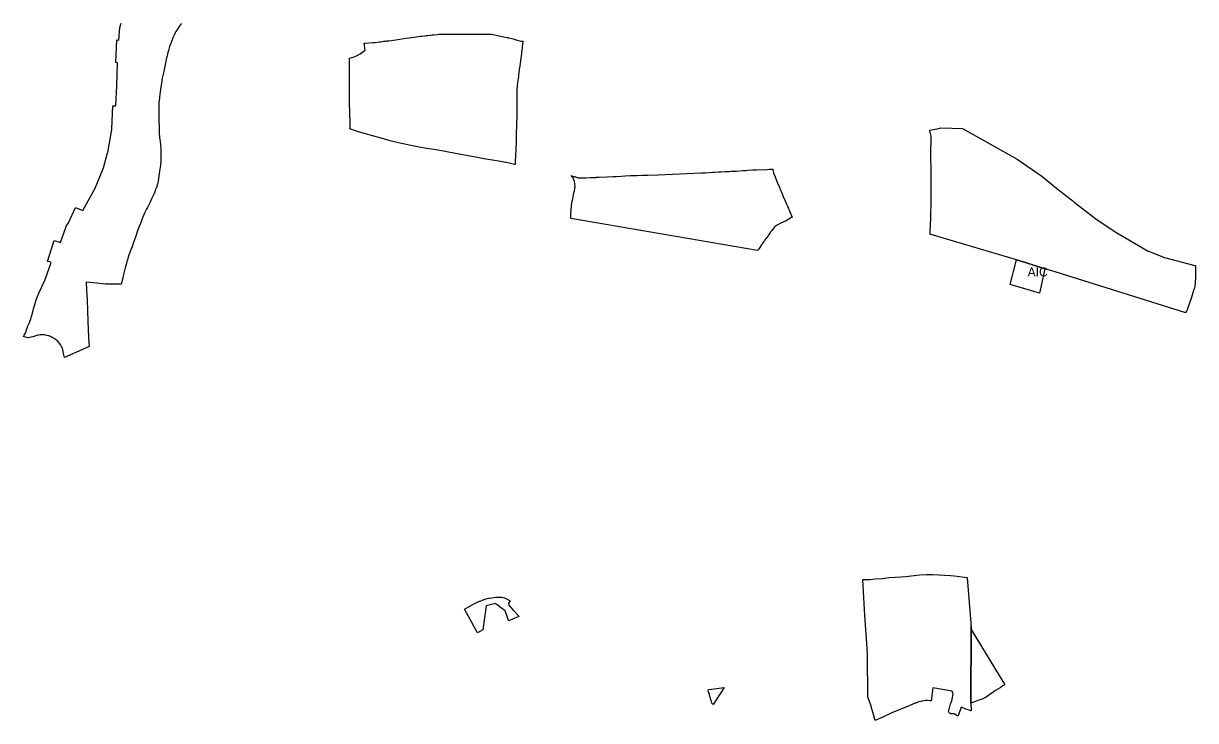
# Model space of a CAD drawing. Extents: x 603332 to 610661, y 4407453 to 4413433.
# Drawn here: x 606609 to 608167, y 4407735 to 4408661 of the extents above; entities that cross this region are included whole.
import ezdxf

# ---------------------------------------------------------------- set-up
doc = ezdxf.new("R2010")
doc.units = 0
for name, color, linetype in [('Sistema General-Activitats i instal·lacions complementàries', 7, 'Continuous'), ('Sistema General-Equipament Privat de Costes', 7, 'Continuous'), ('Sistema General-Espai Lliure Públic', 7, 'Continuous'), ('Sistema General-Espai Lliure Públic-Sòl Rústic', 7, 'Continuous')]:
    doc.layers.add(name, color=color, linetype=linetype)

msp = doc.modelspace()

# ---------------------------------------------------------------- linework, layer by layer
at = {"layer": 'Sistema General-Activitats i instal·lacions complementàries'}
msp.add_lwpolyline([(607967, 4408335.3), (607960, 4408303), (607921, 4408314.2), (607929.2, 4408347), (607941.1, 4408343.4)], close=True, dxfattribs=at)
at = {"layer": 'Sistema General-Equipament Privat de Costes'}
for points in [[(607248.3, 4407897.9), (607248.6, 4407897.8), (607252.2, 4407896.1), (607256.1, 4407893.7), (607254, 4407890.9), (607254.4, 4407888.2), (607257.4, 4407884.8), (607260.4, 4407881.5), (607261.3, 4407880.5), (607267.8, 4407873.4), (607268, 4407873.1), (607263.8, 4407871.4), (607262.3, 4407870.7), (607261.8, 4407870.5), (607261.7, 4407870.4), (607260.1, 4407869.7), (607254.4, 4407867.3), (607254.1, 4407867.9), (607252.4, 4407872.9), (607249.6, 4407880.7), (607241.6, 4407886.5), (607241.6, 4407886.6), (607238.4, 4407888.9), (607238.3, 4407889), (607236.7, 4407890.2), (607224.4, 4407887.3), (607220, 4407855.2), (607213, 4407851.4), (607195.6, 4407882.8), (607198.8, 4407884.5), (607206.5, 4407888.8), (607210.7, 4407891), (607211.3, 4407891.3), (607212.8, 4407892), (607213.1, 4407892.2), (607213.8, 4407892.5), (607214, 4407892.6), (607215.5, 4407893.2), (607216.3, 4407893.5), (607218.8, 4407894.4), (607221.3, 4407895.4), (607221.7, 4407895.5), (607222.2, 4407895.7), (607222.3, 4407895.7), (607222.8, 4407895.9), (607224.8, 4407896.5), (607225.8, 4407896.8), (607227.6, 4407897.2), (607228.6, 4407897.4), (607232.1, 4407897.9), (607236.8, 4407898.6), (607241.7, 4407898.9), (607242.9, 4407898.9), (607244.3, 4407898.7), (607245.3, 4407898.5)], [(607913.8, 4407782.5), (607912.7, 4407781.7), (607912, 4407781.3), (607909.9, 4407779.9), (607907.3, 4407778.2), (607904.3, 4407776.4), (607901.3, 4407774.5), (607890.8, 4407766.9), (607888.8, 4407765.6), (607886.2, 4407764.3), (607883.7, 4407763.1), (607880.6, 4407762.1), (607880.4, 4407762), (607877.8, 4407761.2), (607871.1, 4407758.8), (607868.7, 4407757.9), (607868.7, 4407757.9), (607868.7, 4407763.2), (607868.9, 4407851.8), (607868.9, 4407858.1), (607868.9, 4407859), (607868.9, 4407859), (607868.9, 4407859), (607868.9, 4407860.6), (607868.9, 4407858.9), (607869.1, 4407857.3), (607869.4, 4407855.7), (607869.9, 4407854.1), (607870.2, 4407853.4), (607912.6, 4407784.5)], [(607526.1, 4407756.2), (607524.5, 4407757.7), (607524, 4407759.6), (607523.5, 4407761.3), (607522.7, 4407763.6), (607522.6, 4407764.1), (607522.2, 4407765.5), (607521.4, 4407769.3), (607520.5, 4407771.5), (607519.6, 4407774.2), (607519.8, 4407776.1), (607524.1, 4407776.6), (607540.9, 4407778.4)]]:
    msp.add_lwpolyline(points, close=True, dxfattribs=at)
at = {"layer": 'Sistema General-Espai Lliure Públic'}
msp.add_lwpolyline([(606819.4, 4408661.4), (606818.5, 4408660.2), (606817.2, 4408658.6), (606816.7, 4408657.8), (606813.8, 4408653.3), (606812.2, 4408650.7), (606811.7, 4408649.8), (606811.1, 4408648.7), (606809.8, 4408646), (606808.1, 4408642.4), (606807, 4408639.6), (606804.2, 4408631.7), (606803.8, 4408630.7), (606802.7, 4408627.3), (606802.1, 4408625.3), (606801.5, 4408622.9), (606800.3, 4408618.4), (606799.7, 4408615.8), (606795.9, 4408597.4), (606794, 4408588.5), (606793.6, 4408586.4), (606793.2, 4408584.5), (606792.9, 4408582.4), (606792.4, 4408579.5), (606791.6, 4408573.6), (606790.3, 4408563.7), (606790.1, 4408561.7), (606789.8, 4408558.8), (606789.6, 4408556.7), (606789.4, 4408552.8), (606789.2, 4408548.8), (606789.2, 4408545.5), (606789.2, 4408541.7), (606789.5, 4408531.3), (606789.7, 4408525), (606789.8, 4408520.3), (606790, 4408516), (606790.5, 4408509.2), (606790.7, 4408507.2), (606791.5, 4408500.9), (606791.7, 4408498.5), (606791.9, 4408495), (606792, 4408493.4), (606792.1, 4408489.6), (606792.1, 4408483.4), (606792, 4408479.5), (606791.9, 4408477.3), (606791.7, 4408474.5), (606791.6, 4408473), (606790.9, 4408467.6), (606788.7, 4408452.1), (606788.5, 4408451.1), (606788.2, 4408449.6), (606787.3, 4408446.5), (606786.3, 4408443.2), (606785.2, 4408440.5), (606783.5, 4408436.3), (606780.2, 4408429), (606777.8, 4408423.9), (606776.8, 4408421.8), (606774.2, 4408416.6), (606773.1, 4408414.5), (606771.1, 4408410.9), (606770.2, 4408409), (606768.9, 4408405.9), (606767.7, 4408402.8), (606766.6, 4408400.1), (606764.9, 4408395.5), (606763.3, 4408391.3), (606762.5, 4408389.3), (606761.7, 4408387.2), (606758.8, 4408378.4), (606756.4, 4408371.7), (606754.6, 4408366.3), (606754.3, 4408365.3), (606753.7, 4408364), (606753.1, 4408362.7), (606751.5, 4408358.4), (606750.1, 4408354.7), (606749.6, 4408353.3), (606749.2, 4408352), (606747.6, 4408347.1), (606747.4, 4408346.3), (606747.1, 4408345.3), (606746.8, 4408343.7), (606746.5, 4408342.7), (606744.8, 4408336.3), (606742.1, 4408326), (606741.4, 4408323.1), (606741.1, 4408321.7), (606740.7, 4408319.6), (606740.3, 4408317.5), (606740.2, 4408316.8), (606740, 4408316.5), (606739.5, 4408314.9), (606739.2, 4408314.9), (606724.3, 4408314.7), (606718.6, 4408315), (606707.1, 4408315.9), (606693, 4408317.4), (606693.4, 4408306.7), (606694, 4408293.7), (606694.5, 4408280.1), (606695.1, 4408265.5), (606696.1, 4408244), (606696.9, 4408231.7), (606671, 4408220.5), (606663.9, 4408217.4), (606662.9, 4408222.7), (606662.4, 4408224.7), (606661.7, 4408227.8), (606661.3, 4408229), (606660.8, 4408230.6), (606660.1, 4408232), (606659, 4408233.9), (606658, 4408235.3), (606656.4, 4408237.3), (606655.9, 4408237.8), (606654.2, 4408239.7), (606653.5, 4408240.4), (606652.1, 4408241.4), (606651.1, 4408242.1), (606649.6, 4408243), (606649.1, 4408243.3), (606648.4, 4408243.7), (606646.7, 4408244.5), (606645.3, 4408245.1), (606643.2, 4408245.9), (606642.2, 4408246.2), (606640.6, 4408246.6), (606639.1, 4408247), (606637.2, 4408247.3), (606636.4, 4408247.4), (606635.6, 4408247.4), (606632.7, 4408247.3), (606631.7, 4408247.3), (606629.6, 4408247), (606628.4, 4408246.8), (606627.2, 4408246.4), (606625.4, 4408245.9), (606623.9, 4408245.4), (606621.9, 4408244.6), (606615.4, 4408243.4), (606609.5, 4408245), (606610.5, 4408247), (606612.7, 4408250.5), (606613.2, 4408252.9), (606614.1, 4408255.4), (606615, 4408257.7), (606615.5, 4408259.5), (606615.8, 4408260.2), (606617.3, 4408263.1), (606617.5, 4408263.8), (606618, 4408265.4), (606619.1, 4408268), (606619.8, 4408271.2), (606620.1, 4408272), (606620.5, 4408272.8), (606620.9, 4408275), (606621.9, 4408278.1), (606623, 4408281.8), (606624.7, 4408287.9), (606626.4, 4408293.9), (606629.2, 4408300.8), (606630, 4408302.8), (606633.4, 4408310.2), (606638.4, 4408321.2), (606646.4, 4408343.6), (606643.9, 4408344.4), (606641.3, 4408345.1), (606650.2, 4408372.8), (606658.8, 4408370.1), (606666.3, 4408391.5), (606666.3, 4408391.7), (606667.4, 4408393.7), (606669.2, 4408396.3), (606669.2, 4408396.3), (606678.7, 4408416.9), (606688.5, 4408412.5), (606704.9, 4408442.4), (606704.9, 4408442.4), (606715.7, 4408469.6), (606721.4, 4408489.4), (606721.5, 4408490), (606727, 4408520.6), (606727, 4408521.1), (606728.5, 4408551.8), (606732.3, 4408551.7), (606733.4, 4408578.3), (606734.6, 4408609), (606732.4, 4408609.4), (606733.6, 4408639.4), (606736.4, 4408639.2), (606737.8, 4408656.1), (606739.5, 4408661.8)], dxfattribs=at)
for points in [[(607263, 4408473.7), (607262.3, 4408473.8), (607251.5, 4408476.3), (607249.9, 4408476.7), (607241.4, 4408478.1), (607235.5, 4408479.1), (607221.4, 4408481.6), (607216.9, 4408482.4), (607210.2, 4408483.6), (607183.6, 4408488.4), (607170.1, 4408491), (607157.8, 4408493.2), (607151.9, 4408494.2), (607145.1, 4408495.3), (607133.2, 4408497.4), (607126.4, 4408498.7), (607113.9, 4408501.2), (607108, 4408502.5), (607096.7, 4408505.3), (607092.3, 4408506.6), (607081.7, 4408509.6), (607075.1, 4408511.5), (607062.2, 4408515.1), (607053.5, 4408517.6), (607043.2, 4408521.4), (607043.5, 4408522.3), (607043.6, 4408528.7), (607043.1, 4408542.5), (607043.1, 4408542.6), (607042.8, 4408556.5), (607042.8, 4408558), (607042.9, 4408575.4), (607043, 4408585.4), (607042.6, 4408615.2), (607045.8, 4408616), (607049, 4408616.8), (607051.1, 4408617.9), (607052.8, 4408618.8), (607053.9, 4408619.4), (607056.9, 4408621), (607059.9, 4408623.2), (607063.5, 4408625.9), (607062.5, 4408635), (607063.8, 4408635.1), (607073.7, 4408635.9), (607076.7, 4408636.2), (607082.5, 4408636.8), (607083.3, 4408636.9), (607083.7, 4408637), (607083.7, 4408637), (607084.2, 4408637.1), (607084.5, 4408637.1), (607086.2, 4408637.3), (607088.4, 4408637.6), (607089.4, 4408637.7), (607089.7, 4408637.7), (607089.7, 4408637.7), (607089.7, 4408637.7), (607089.8, 4408637.7), (607089.9, 4408637.7), (607089.9, 4408637.7), (607089.9, 4408637.7), (607090, 4408637.8), (607090.9, 4408637.9), (607092.6, 4408638.1), (607092.9, 4408638.1), (607093.7, 4408638.2), (607095.1, 4408638.4), (607098.6, 4408638.8), (607107.1, 4408640), (607118.3, 4408641.6), (607122.2, 4408642.2), (607128.9, 4408643.2), (607136.7, 4408644.3), (607137.1, 4408644.3), (607138.7, 4408644.6), (607142.7, 4408645.1), (607144.7, 4408645.3), (607145.2, 4408645.4), (607146.8, 4408645.5), (607149.9, 4408645.8), (607150.7, 4408645.9), (607150.8, 4408645.9), (607152.8, 4408646.1), (607155.2, 4408646.3), (607159.2, 4408646.7), (607161.6, 4408647), (607164.2, 4408647.2), (607170.8, 4408647.2), (607170.9, 4408647.2), (607171.2, 4408647.2), (607171.5, 4408647.2), (607171.5, 4408647.2), (607171.6, 4408647.2), (607171.6, 4408647.2), (607178, 4408647.3), (607183.1, 4408647.3), (607183.1, 4408647.3), (607183.3, 4408647.3), (607183.9, 4408647.3), (607183.9, 4408647.3), (607184.2, 4408647.3), (607190.1, 4408647.3), (607195, 4408647.3), (607195.4, 4408647.3), (607195.4, 4408647.3), (607195.5, 4408647.3), (607195.5, 4408647.3), (607195.6, 4408647.3), (607201.1, 4408647.3), (607201.3, 4408647.3), (607201.4, 4408647.3), (607201.5, 4408647.3), (607205.2, 4408647.3), (607213.5, 4408647.3), (607226.1, 4408647.3), (607230, 4408647.3), (607232, 4408646.9), (607241.3, 4408645), (607252, 4408642.8), (607253.1, 4408642.5), (607254.2, 4408642.3), (607254.4, 4408642.2), (607258.4, 4408641.2), (607260.1, 4408640.7), (607263.9, 4408639.7), (607264.2, 4408639.6), (607264.2, 4408639.6), (607264.3, 4408639.6), (607264.4, 4408639.6), (607270.4, 4408638), (607273.3, 4408637.9), (607273.2, 4408637.6), (607273.1, 4408636.1), (607272.8, 4408634.2), (607271.8, 4408625.5), (607271.6, 4408623.7), (607271.6, 4408623.1), (607271.5, 4408622.5), (607271.4, 4408621.6), (607270.1, 4408612.1), (607269, 4408604.4), (607268.5, 4408600.4), (607268.4, 4408599.8), (607267.4, 4408592.2), (607267.3, 4408591.7), (607267.3, 4408591.4), (607267.2, 4408591), (607267.2, 4408590.8), (607267.2, 4408590.7), (607267.2, 4408590.7), (607266.8, 4408587.7), (607266.6, 4408585.8), (607265.8, 4408578.9), (607265.8, 4408578.9), (607265.8, 4408578.9), (607265.8, 4408578.8), (607265.6, 4408577), (607265.4, 4408574.5), (607265.3, 4408574.1), (607265.4, 4408566.9), (607265.4, 4408565.7), (607265.4, 4408564.6), (607265.4, 4408560.7), (607265.4, 4408554.9), (607265.4, 4408551.4), (607265.4, 4408549.7), (607265.2, 4408542.6), (607265.1, 4408537.5), (607265.1, 4408537.4), (607265, 4408536.1), (607264.8, 4408530.3), (607264.7, 4408526), (607264.7, 4408525.8), (607264.6, 4408521.5), (607264.5, 4408519.2), (607264.5, 4408512.9), (607264.5, 4408511.2), (607264.4, 4408506.8), (607264.4, 4408506), (607264.4, 4408506), (607264.4, 4408505.9), (607264.4, 4408505.8), (607264.3, 4408505.1), (607264.3, 4408505), (607264.3, 4408505), (607264.3, 4408504.4), (607263.8, 4408494.1), (607263.8, 4408494), (607263.8, 4408493.8), (607263.8, 4408493.6), (607263.8, 4408493.6), (607263.8, 4408493.3), (607263.7, 4408492.1), (607263.7, 4408491.5), (607263.5, 4408488.7), (607263.2, 4408482.8), (607263.1, 4408480.4), (607263.1, 4408479.6), (607263.1, 4408479.1), (607263.1, 4408479), (607263.1, 4408478.7), (607263.1, 4408478.4), (607263, 4408476), (607263, 4408475.2), (607263, 4408474)], [(607585, 4408359.5), (607336.8, 4408402.1), (607336.9, 4408408.7), (607338.2, 4408423.2), (607339.6, 4408428.4), (607341.1, 4408436.4), (607341.7, 4408438.7), (607342.3, 4408441.7), (607342.5, 4408444.7), (607342.4, 4408448.9), (607342, 4408450.9), (607341.4, 4408452.8), (607340.6, 4408454.7), (607339.6, 4408456.4), (607339.3, 4408456.9), (607337.6, 4408459.1), (607339.3, 4408458.5), (607340.5, 4408458.1), (607341.1, 4408457.8), (607341.2, 4408457.8), (607341.5, 4408457.7), (607341.8, 4408457.6), (607342, 4408457.6), (607342, 4408457.6), (607342.1, 4408457.6), (607342.2, 4408457.5), (607342.2, 4408457.5), (607342.4, 4408457.5), (607342.5, 4408457.5), (607342.7, 4408457.4), (607343, 4408457.3), (607343.9, 4408457.1), (607344.2, 4408457), (607345.4, 4408456.7), (607345.6, 4408456.6), (607345.8, 4408456.5), (607345.8, 4408456.5), (607346.9, 4408456.2), (607346.9, 4408456.2), (607347.4, 4408456.1), (607347.9, 4408456), (607347.9, 4408456), (607348.8, 4408456), (607348.9, 4408456), (607348.9, 4408456), (607349.7, 4408456), (607349.8, 4408456), (607351.1, 4408456), (607351.4, 4408456), (607351.4, 4408456), (607351.4, 4408456), (607351.4, 4408456), (607351.5, 4408456), (607351.6, 4408456), (607351.6, 4408456), (607351.7, 4408456), (607352.2, 4408456.1), (607357.5, 4408456.3), (607362.8, 4408456.5), (607364.2, 4408456.6), (607364.6, 4408456.6), (607364.7, 4408456.6), (607365.4, 4408456.6), (607365.4, 4408456.6), (607369.9, 4408456.8), (607369.9, 4408456.8), (607369.9, 4408456.8), (607370.1, 4408456.8), (607370.9, 4408456.9), (607371, 4408456.9), (607371.2, 4408456.9), (607374.6, 4408457), (607384.6, 4408457.4), (607393.2, 4408457.8), (607393.8, 4408457.8), (607397.6, 4408458), (607403.8, 4408458.2), (607409.2, 4408458.7), (607416.2, 4408459.3), (607424.7, 4408459.4), (607431.2, 4408459.5), (607432.7, 4408459.5), (607436.5, 4408459.6), (607437.8, 4408459.6), (607437.9, 4408459.6), (607438.4, 4408459.6), (607438.9, 4408459.6), (607438.9, 4408459.6), (607439, 4408459.6), (607439.1, 4408459.6), (607439.1, 4408459.6), (607453.2, 4408460.3), (607510.2, 4408462.7), (607513.9, 4408462.9), (607513.9, 4408462.9), (607514, 4408462.9), (607514.6, 4408463), (607515.7, 4408463), (607525.1, 4408463.5), (607526.8, 4408463.6), (607526.9, 4408463.6), (607527.5, 4408463.6), (607533.8, 4408464), (607536.1, 4408464.1), (607536.2, 4408464.1), (607536.3, 4408464.1), (607536.3, 4408464.1), (607536.3, 4408464.1), (607536.3, 4408464.1), (607536.3, 4408464.1), (607536.4, 4408464.1), (607536.5, 4408464.1), (607536.5, 4408464.1), (607542, 4408464.4), (607547.2, 4408464.7), (607547.3, 4408464.7), (607547.5, 4408464.7), (607550.2, 4408464.9), (607550.5, 4408464.9), (607550.7, 4408464.9), (607550.7, 4408464.9), (607551.2, 4408464.9), (607552.4, 4408465), (607556.3, 4408465.2), (607556.4, 4408465.2), (607556.4, 4408465.2), (607556.4, 4408465.2), (607556.6, 4408465.2), (607565.9, 4408465.8), (607569.7, 4408466), (607572, 4408466.2), (607579, 4408466.6), (607581.5, 4408466.7), (607582.2, 4408466.8), (607582.3, 4408466.8), (607582.6, 4408466.8), (607582.8, 4408466.8), (607582.9, 4408466.8), (607583.1, 4408466.8), (607583.6, 4408466.8), (607597.7, 4408467.4), (607597.7, 4408467.4), (607597.9, 4408467.4), (607601, 4408467.5), (607601.1, 4408467.5), (607601.1, 4408467.5), (607601.2, 4408467.5), (607601.2, 4408467.5), (607601.3, 4408467.5), (607601.3, 4408467.5), (607605.4, 4408467.7), (607605.6, 4408466.2), (607605.7, 4408465.6), (607605.7, 4408465.4), (607606.4, 4408462.6), (607606.5, 4408462.4), (607607.3, 4408460.1), (607607.4, 4408459.9), (607608.6, 4408457.3), (607610.2, 4408452.6), (607611.1, 4408450.3), (607613.3, 4408445.3), (607613.6, 4408444.5), (607614.5, 4408442.6), (607615.3, 4408440.7), (607615.8, 4408439.7), (607615.8, 4408439.6), (607615.9, 4408439.5), (607615.9, 4408439.5), (607615.9, 4408439.4), (607615.9, 4408439.4), (607615.9, 4408439.4), (607615.9, 4408439.4), (607615.9, 4408439.4), (607616.1, 4408438.9), (607616.5, 4408437.9), (607616.8, 4408437.2), (607616.9, 4408437.1), (607618.5, 4408432.6), (607618.7, 4408432), (607618.8, 4408431.9), (607620.7, 4408427.6), (607623.5, 4408421.3), (607624.9, 4408418.4), (607625, 4408418), (607625, 4408417.9), (607625.4, 4408417.3), (607626.1, 4408415.7), (607626.3, 4408415.2), (607626.3, 4408415.1), (607626.4, 4408415), (607626.4, 4408414.9), (607626.4, 4408414.9), (607626.7, 4408414.1), (607626.9, 4408413.6), (607628, 4408411.1), (607630.9, 4408403.9), (607630.5, 4408403.6), (607630.3, 4408403.5), (607630.3, 4408403.5), (607629.9, 4408403.2), (607629.8, 4408403.2), (607628.9, 4408402.7), (607623.1, 4408399.1), (607616.1, 4408395.8), (607611.2, 4408393.3), (607608.4, 4408391.6), (607607.3, 4408390.5), (607607.2, 4408390.4), (607607.2, 4408390.4), (607607.1, 4408390.3), (607605.7, 4408388.5), (607604, 4408386.1), (607603.6, 4408385.6), (607602.8, 4408384.6), (607602.5, 4408384.2), (607602.4, 4408384.1), (607602.4, 4408384.1), (607602.2, 4408383.9), (607601.9, 4408383.5), (607601.9, 4408383.5), (607601.9, 4408383.4), (607601.9, 4408383.4), (607601.8, 4408383.3), (607601.7, 4408383.2), (607601.7, 4408383.1), (607600.1, 4408380.8), (607600, 4408380.7), (607597.7, 4408377.4), (607597.2, 4408376.8), (607596.4, 4408375.6), (607596.3, 4408375.5), (607594.2, 4408372.5), (607593.5, 4408371.5), (607593.4, 4408371.4), (607591.8, 4408369.2), (607591.2, 4408368.4), (607590.8, 4408367.9), (607586.6, 4408361.5), (607586.5, 4408361.4), (607585.9, 4408360.6)], [(607863.6, 4407924.6), (607868.9, 4407859), (607868.9, 4407859), (607868.9, 4407859), (607868.9, 4407858.1), (607868.9, 4407851.8), (607868.7, 4407763.2), (607868.7, 4407757.9), (607868.7, 4407757.9), (607868.7, 4407757.9), (607868.9, 4407747.6), (607868.5, 4407747.8), (607867.5, 4407748.1), (607862, 4407750), (607860, 4407750.7), (607856.8, 4407751.9), (607855.6, 4407752.3), (607852, 4407742.4), (607851.2, 4407740.4), (607849.5, 4407741.6), (607849.3, 4407741.8), (607849.1, 4407742), (607848.9, 4407742.1), (607848.8, 4407742.2), (607848.6, 4407742.3), (607848.4, 4407742.4), (607848.3, 4407742.5), (607848, 4407742.7), (607847.9, 4407742.8), (607847.8, 4407742.8), (607847.5, 4407743), (607847.2, 4407743.1), (607846.9, 4407743.2), (607846.8, 4407743.3), (607846.7, 4407743.3), (607846.5, 4407743.4), (607846.4, 4407743.4), (607846.1, 4407743.5), (607846.1, 4407743.5), (607845.8, 4407743.6), (607845.5, 4407743.7), (607845.2, 4407743.7), (607844.9, 4407743.8), (607844.7, 4407743.8), (607844.6, 4407743.8), (607844.3, 4407743.8), (607844, 4407743.8), (607843.7, 4407743.9), (607843.3, 4407743.9), (607843.1, 4407743.8), (607843, 4407743.8), (607842.7, 4407743.8), (607842.6, 4407743.8), (607842.4, 4407743.8), (607842.4, 4407743.8), (607842.1, 4407743.7), (607841.8, 4407743.7), (607841.7, 4407743.6), (607841.5, 4407743.6), (607839, 4407746.1), (607841.7, 4407756.7), (607842.1, 4407757.7), (607843.4, 4407761), (607845, 4407769.6), (607843.7, 4407773.6), (607818.2, 4407778.3), (607815.6, 4407760.8), (607813.9, 4407761.1), (607810.8, 4407761.3), (607808.5, 4407761.2), (607806.7, 4407761.1), (607804, 4407760.6), (607802.8, 4407760.4), (607802.1, 4407760.2), (607799.1, 4407759.4), (607796.4, 4407758.4), (607795.4, 4407758.1), (607795, 4407757.9), (607794.7, 4407757.8), (607788.5, 4407755.2), (607787.3, 4407754.6), (607785.9, 4407753.8), (607764.3, 4407745.6), (607751.7, 4407739.2), (607741.6, 4407734.7), (607738.5, 4407745.8), (607736.8, 4407750.2), (607736.7, 4407750.6), (607736.3, 4407753), (607733, 4407762.1), (607731.6, 4407766), (607731.2, 4407821.8), (607730.6, 4407831.3), (607727.8, 4407874.1), (607727.8, 4407874.5), (607725, 4407922.2), (607727.3, 4407922.2), (607735.2, 4407922.4), (607741.5, 4407923), (607751.1, 4407923.6), (607760.1, 4407924.7), (607767.9, 4407925.2), (607775.4, 4407925.8), (607781.8, 4407926.2), (607800.7, 4407928.3), (607809.5, 4407928.8), (607811.8, 4407929), (607817.9, 4407928.8), (607841.7, 4407927.6), (607842, 4407927.5), (607850.5, 4407926.6), (607863, 4407924.7)]]:
    msp.add_lwpolyline(points, close=True, dxfattribs=at)
at = {"layer": 'Sistema General-Espai Lliure Públic-Sòl Rústic'}
msp.add_lwpolyline([(607967, 4408335.3), (607941.1, 4408343.4), (607929.2, 4408347), (607821.6, 4408378.9), (607817, 4408380.2), (607814.6, 4408380.9), (607814.7, 4408382.9), (607814.7, 4408384.9), (607814.7, 4408384.9), (607815.4, 4408403.1), (607815.4, 4408403.7), (607815.4, 4408403.9), (607815.4, 4408405.7), (607815.5, 4408407.8), (607815.6, 4408422), (607815.7, 4408428.3), (607815.7, 4408428.6), (607815.8, 4408436.3), (607815.8, 4408440.7), (607815.9, 4408464.9), (607815.4, 4408486.4), (607815.6, 4408511.7), (607814.4, 4408516.9), (607814, 4408518.8), (607813.9, 4408519.4), (607813.9, 4408519.5), (607821, 4408521), (607825.5, 4408521.9), (607828.6, 4408522.5), (607857.3, 4408521.8), (607929.9, 4408480.9), (607962.8, 4408458.5), (607982.2, 4408442.4), (607982.8, 4408442.1), (607996.6, 4408431.2), (608004, 4408425.4), (608005.7, 4408424), (608034.5, 4408401.6), (608060.4, 4408384.5), (608104.1, 4408358.5), (608104.8, 4408358.6), (608125.8, 4408350.3), (608166.3, 4408339.6), (608166.3, 4408339.6), (608166.3, 4408339.6), (608166.3, 4408339.5), (608166.9, 4408339.4), (608166.9, 4408338.5), (608167, 4408332.7), (608167.2, 4408326.2), (608167.1, 4408326.2), (608167.1, 4408326.1), (608167.1, 4408326.1), (608167.1, 4408323.4), (608166.8, 4408316.8), (608166.1, 4408311.8), (608166, 4408311.5), (608165.6, 4408309.8), (608164.6, 4408306.4), (608161.2, 4408295.8), (608155, 4408278.6), (608154.9, 4408278.4), (608154.4, 4408277.2), (608154.2, 4408276.8), (607980.8, 4408331)], close=True, dxfattribs=at)

# ---------------------------------------------------------------- texts
at = {"layer": 'Sistema General-Activitats i instal·lacions complementàries'}
msp.add_text('AIC', height=12, dxfattribs=at).set_placement((607944, 4408325))

doc.saveas('drawing.dxf')
